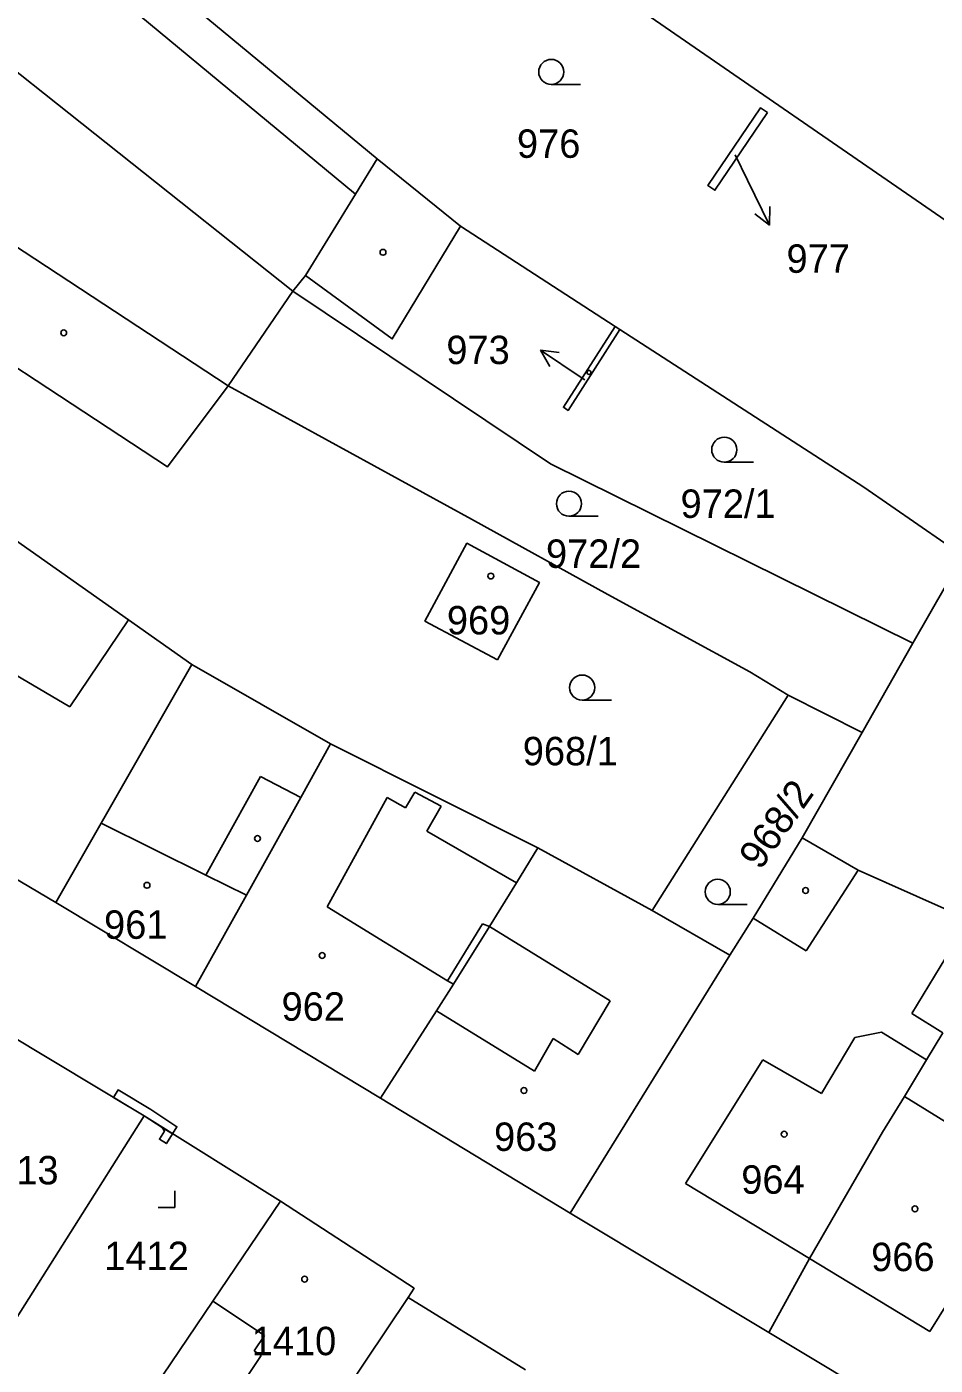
# Model space of a CAD drawing. Extents: x -600849 to -599899, y -1204328 to -1203436.
# Drawn here: x -600294.6 to -600240.2, y -1203715.5 to -1203635.4 of the extents above; entities that cross this region are included whole.
import ezdxf

# ---------------------------------------------------------------- set-up
doc = ezdxf.new("R2010")
doc.units = 0
for name, color, linetype in [('Vrstva 1', 7, 'Continuous'), ('Vrstva 13', 7, 'Continuous'), ('Vrstva 2', 7, 'Continuous'), ('Vrstva 3', 7, 'Continuous'), ('Vrstva 4', 7, 'Continuous'), ('Vrstva 5', 7, 'Continuous'), ('Vrstva 7', 7, 'Continuous')]:
    doc.layers.add(name, color=color, linetype=linetype)

msp = doc.modelspace()

# ---------------------------------------------------------------- linework, layer by layer
at = {"layer": 'Vrstva 1'}
for p, q in [((-600231.37, -1203652.7), (-600262.78, -1203631.03)), ((-600268.62, -1203647.36), (-600259.37, -1203653.35)), ((-600259.09, -1203653.54), (-600259.37, -1203653.35)), ((-600238.52, -1203666.97), (-600241.56, -1203672.31)), ((-600241.56, -1203672.31), (-600244.59, -1203677.64)), ((-600276.39, -1203678.32), (-600284.69, -1203673.58)), ((-600257.16, -1203688.3), (-600249.03, -1203675.41)), ((-600249.03, -1203675.41), (-600244.59, -1203677.64)), ((-600244.59, -1203677.64), (-600248.18, -1203683.94)), ((-600264, -1203684.55), (-600276.39, -1203678.32)), ((-600257.16, -1203688.3), (-600264, -1203684.55)), ((-600292.82, -1203687.81), (-600284.47, -1203692.84)), ((-600252.52, -1203690.96), (-600257.16, -1203688.3)), ((-600262.06, -1203706.4), (-600252.52, -1203690.96)), ((-600284.47, -1203692.84), (-600273.41, -1203699.53)), ((-600287.54, -1203700.59), (-600295.8, -1203695.61)), ((-600273.41, -1203699.53), (-600262.06, -1203706.4)), ((-600287.54, -1203700.59), (-600299.56, -1203719.57)), ((-600279.38, -1203705.68), (-600287.54, -1203700.59)), ((-600262.06, -1203706.4), (-600250.17, -1203713.54)), ((-600264.74, -1203715.78), (-600271.76, -1203711.44))]:
    msp.add_line(p, q, dxfattribs=at)
for points in [[(-600292.5, -1203627.7), (-600273.6, -1203643.33), (-600268.62, -1203647.36)], [(-600299.45, -1203634.74), (-600294.22, -1203629.44), (-600274.9, -1203645.44), (-600277.9, -1203650.3), (-600272.7, -1203654.1), (-600268.62, -1203647.36)], [(-600299.45, -1203634.74), (-600278.65, -1203651.25), (-600263.23, -1203661.57), (-600241.56, -1203672.31)], [(-600282.53, -1203656.9), (-600299.5, -1203645.77), (-600309.22, -1203638.82)], [(-600250.25, -1203640.55), (-600253.4, -1203645.21), (-600253.82, -1203644.93), (-600250.67, -1203640.27), (-600250.25, -1203640.55)], [(-600308.36, -1203656.62), (-600303.33, -1203650.46), (-600286.14, -1203661.75), (-600282.53, -1203656.9)], [(-600259.37, -1203653.35), (-600262.47, -1203658.19), (-600262.19, -1203658.38), (-600259.09, -1203653.54)], [(-600259.09, -1203653.54), (-600244.5, -1203662.97), (-600239.65, -1203666.33)], [(-600282.53, -1203656.9), (-600267.96, -1203664.88), (-600259.8, -1203669.39), (-600251.31, -1203674.02), (-600249.03, -1203675.41)], [(-600284.69, -1203673.58), (-600288.48, -1203670.91), (-600297.15, -1203664.8), (-600299.96, -1203662.82)], [(-600266.4, -1203673.31), (-600263.9, -1203668.68), (-600268.24, -1203666.33), (-600270.75, -1203670.98), (-600266.4, -1203673.31)], [(-600292.82, -1203687.81), (-600290.12, -1203683.08), (-600284.69, -1203673.58)], [(-600284.47, -1203692.84), (-600281.43, -1203687.38), (-600278.18, -1203681.54), (-600276.39, -1203678.32)], [(-600308.08, -1203678.72), (-600300.83, -1203683.09), (-600292.82, -1203687.81)], [(-600248.18, -1203683.94), (-600251.12, -1203688.76), (-600252.52, -1203690.96)], [(-600236.19, -1203689.73), (-600244.83, -1203685.88), (-600248.18, -1203683.94)], [(-600266.88, -1203689.25), (-600265.28, -1203686.64), (-600264, -1203684.55)], [(-600273.41, -1203699.53), (-600270.06, -1203694.3), (-600269.05, -1203692.71), (-600266.88, -1203689.25)], [(-600250.17, -1203713.54), (-600247.75, -1203709.12), (-600243.37, -1203701.56), (-600242.07, -1203699.42), (-600240.75, -1203697.24), (-600239.77, -1203695.61)], [(-600279.38, -1203705.68), (-600283.43, -1203711.66), (-600290.92, -1203722.73)], [(-600271.76, -1203711.44), (-600271.4, -1203710.89), (-600279.38, -1203705.68)], [(-600271.76, -1203711.44), (-600276.85, -1203719.07), (-600282.24, -1203727.06), (-600282.09, -1203728.15)], [(-600250.17, -1203713.54), (-600242.44, -1203718.18), (-600240.17, -1203717.65)]]:
    msp.add_lwpolyline(points, dxfattribs=at)
at = {"layer": 'Vrstva 13'}
for points in [[(-600286.46, -1203701.27), (-600285.85, -1203701.65), (-600285.59, -1203701.23), (-600287.14, -1203700.2), (-600289.11, -1203699.03), (-600289.38, -1203699.48), (-600287.54, -1203700.59)], [(-600285.85, -1203701.65), (-600286.46, -1203701.27), (-600286.33, -1203701.49), (-600286.63, -1203701.98), (-600286.21, -1203702.24)]]:
    msp.add_lwpolyline(points, close=True, dxfattribs=at)
at = {"layer": 'Vrstva 3'}
for p, q in [((-600263.193, -1203638.88), (-600261.443, -1203638.88)), ((-600252.843, -1203661.48), (-600251.093, -1203661.48)), ((-600262.133, -1203664.71), (-600260.383, -1203664.71)), ((-600261.343, -1203675.71), (-600259.593, -1203675.71)), ((-600253.233, -1203687.93), (-600251.483, -1203687.93)), ((-600285.71, -1203706.07), (-600285.71, -1203705.07)), ((-600286.711, -1203706.07), (-600285.71, -1203706.07))]:
    msp.add_line(p, q, dxfattribs=at)
for centre in [(-600263.193, -1203638.13), (-600252.843, -1203660.73), (-600262.133, -1203663.96), (-600261.343, -1203674.96), (-600253.233, -1203687.18)]:
    msp.add_circle(centre, 0.75, dxfattribs=at)
at = {"layer": 'Vrstva 4'}
for p, q in [((-600274.9, -1203645.44), (-600273.6, -1203643.33)), ((-600277.9, -1203650.3), (-600278.65, -1203651.25)), ((-600282.53, -1203656.9), (-600278.65, -1203651.25)), ((-600291.99, -1203676.11), (-600288.48, -1203670.91)), ((-600299.99, -1203671.42), (-600291.99, -1203676.11)), ((-600283.85, -1203686.18), (-600280.58, -1203680.28)), ((-600280.58, -1203680.28), (-600278.18, -1203681.54)), ((-600276.59, -1203688.08), (-600273.01, -1203681.53)), ((-600273.01, -1203681.53), (-600271.92, -1203682.15)), ((-600271.92, -1203682.15), (-600271.35, -1203681.22)), ((-600271.35, -1203681.22), (-600269.77, -1203682.05)), ((-600269.77, -1203682.05), (-600270.63, -1203683.55)), ((-600290.12, -1203683.08), (-600283.85, -1203686.18)), ((-600270.63, -1203683.55), (-600265.28, -1203686.64)), ((-600283.85, -1203686.18), (-600281.43, -1203687.38)), ((-600244.83, -1203685.88), (-600247.94, -1203690.71)), ((-600276.59, -1203688.08), (-600269.4, -1203692.5)), ((-600247.94, -1203690.71), (-600251.12, -1203688.76)), ((-600269.4, -1203692.5), (-600267.3, -1203689.1)), ((-600266.88, -1203689.25), (-600267.3, -1203689.1)), ((-600259.67, -1203693.7), (-600266.88, -1203689.25)), ((-600238.92, -1203689.99), (-600241.62, -1203694.46)), ((-600269.4, -1203692.5), (-600269.05, -1203692.71)), ((-600261.59, -1203696.92), (-600259.67, -1203693.7)), ((-600270.06, -1203694.3), (-600264.19, -1203697.91)), ((-600241.62, -1203694.46), (-600239.77, -1203695.61)), ((-600264.19, -1203697.91), (-600263.07, -1203695.96)), ((-600263.07, -1203695.96), (-600261.59, -1203696.92)), ((-600247.03, -1203699.25), (-600245.03, -1203695.89)), ((-600245.03, -1203695.89), (-600243.43, -1203695.58)), ((-600240.75, -1203697.24), (-600243.43, -1203695.58)), ((-600255.17, -1203704.63), (-600250.53, -1203697.24)), ((-600250.53, -1203697.24), (-600247.03, -1203699.25)), ((-600242.07, -1203699.42), (-600239.34, -1203701.09)), ((-600247.75, -1203709.12), (-600255.17, -1203704.63)), ((-600240.54, -1203713.49), (-600235.96, -1203706.04)), ((-600240.54, -1203713.49), (-600247.75, -1203709.12)), ((-600280.35, -1203713.72), (-600283.43, -1203711.66)), ((-600280.96, -1203714.64), (-600280.35, -1203713.72)), ((-600287.29, -1203724.99), (-600280.55, -1203714.91)), ((-600280.55, -1203714.91), (-600280.96, -1203714.64))]:
    msp.add_line(p, q, dxfattribs=at)
at = {"layer": 'Vrstva 5'}
for centre, radius in [((-600273.257, -1203648.919), 0.175), ((-600292.357, -1203653.739), 0.175), ((-600260.935, -1203656.109), 0.117), ((-600266.807, -1203668.289), 0.175), ((-600280.767, -1203683.989), 0.175), ((-600287.377, -1203686.789), 0.175), ((-600247.977, -1203687.099), 0.175), ((-600276.897, -1203690.989), 0.175), ((-600264.827, -1203699.069), 0.175), ((-600249.257, -1203701.679), 0.175), ((-600241.437, -1203706.149), 0.175), ((-600277.947, -1203710.349), 0.175)]:
    msp.add_circle(centre, radius, dxfattribs=at)
at = {"layer": 'Vrstva 7'}
for p, q in [((-600252.2, -1203643.09), (-600251.45, -1203644.61)), ((-600251.45, -1203644.61), (-600250.134, -1203647.307)), ((-600250.134, -1203647.307), (-600250.123, -1203646.188)), ((-600250.134, -1203647.307), (-600251.024, -1203646.627)), ((-600261.34, -1203656.45), (-600263.828, -1203654.772)), ((-600263.828, -1203654.772), (-600262.718, -1203654.917)), ((-600263.828, -1203654.772), (-600263.278, -1203655.747)), ((-600261.18, -1203656.56), (-600261.34, -1203656.45))]:
    msp.add_line(p, q, dxfattribs=at)

# ---------------------------------------------------------------- texts
at = {"layer": 'Vrstva 2'}
for s, p in [('976', (-600265.245, -1203643.27)), ('977', (-600249.12, -1203650.148)), ('973', (-600269.47, -1203655.61)), ('972/1', (-600255.458, -1203664.81)), ('972/2', (-600263.508, -1203667.8)), ('969', (-600269.435, -1203671.78)), ('968/1', (-600264.898, -1203679.61)), ('961', (-600289.945, -1203689.99)), ('962', (-600279.325, -1203694.89)), ('963', (-600266.615, -1203702.68)), ('1413', (-600297.724, -1203704.68)), ('964', (-600251.825, -1203705.24)), ('1412', (-600289.934, -1203709.81)), ('966', (-600244.055, -1203709.87)), ('1410', (-600281.114, -1203714.9))]:
    msp.add_text(s, height=1.7, dxfattribs=at).set_placement(p)
msp.add_text('968/2', height=1.7, rotation=55, dxfattribs=at).set_placement((-600250.685, -1203685.939))

doc.saveas('drawing.dxf')
